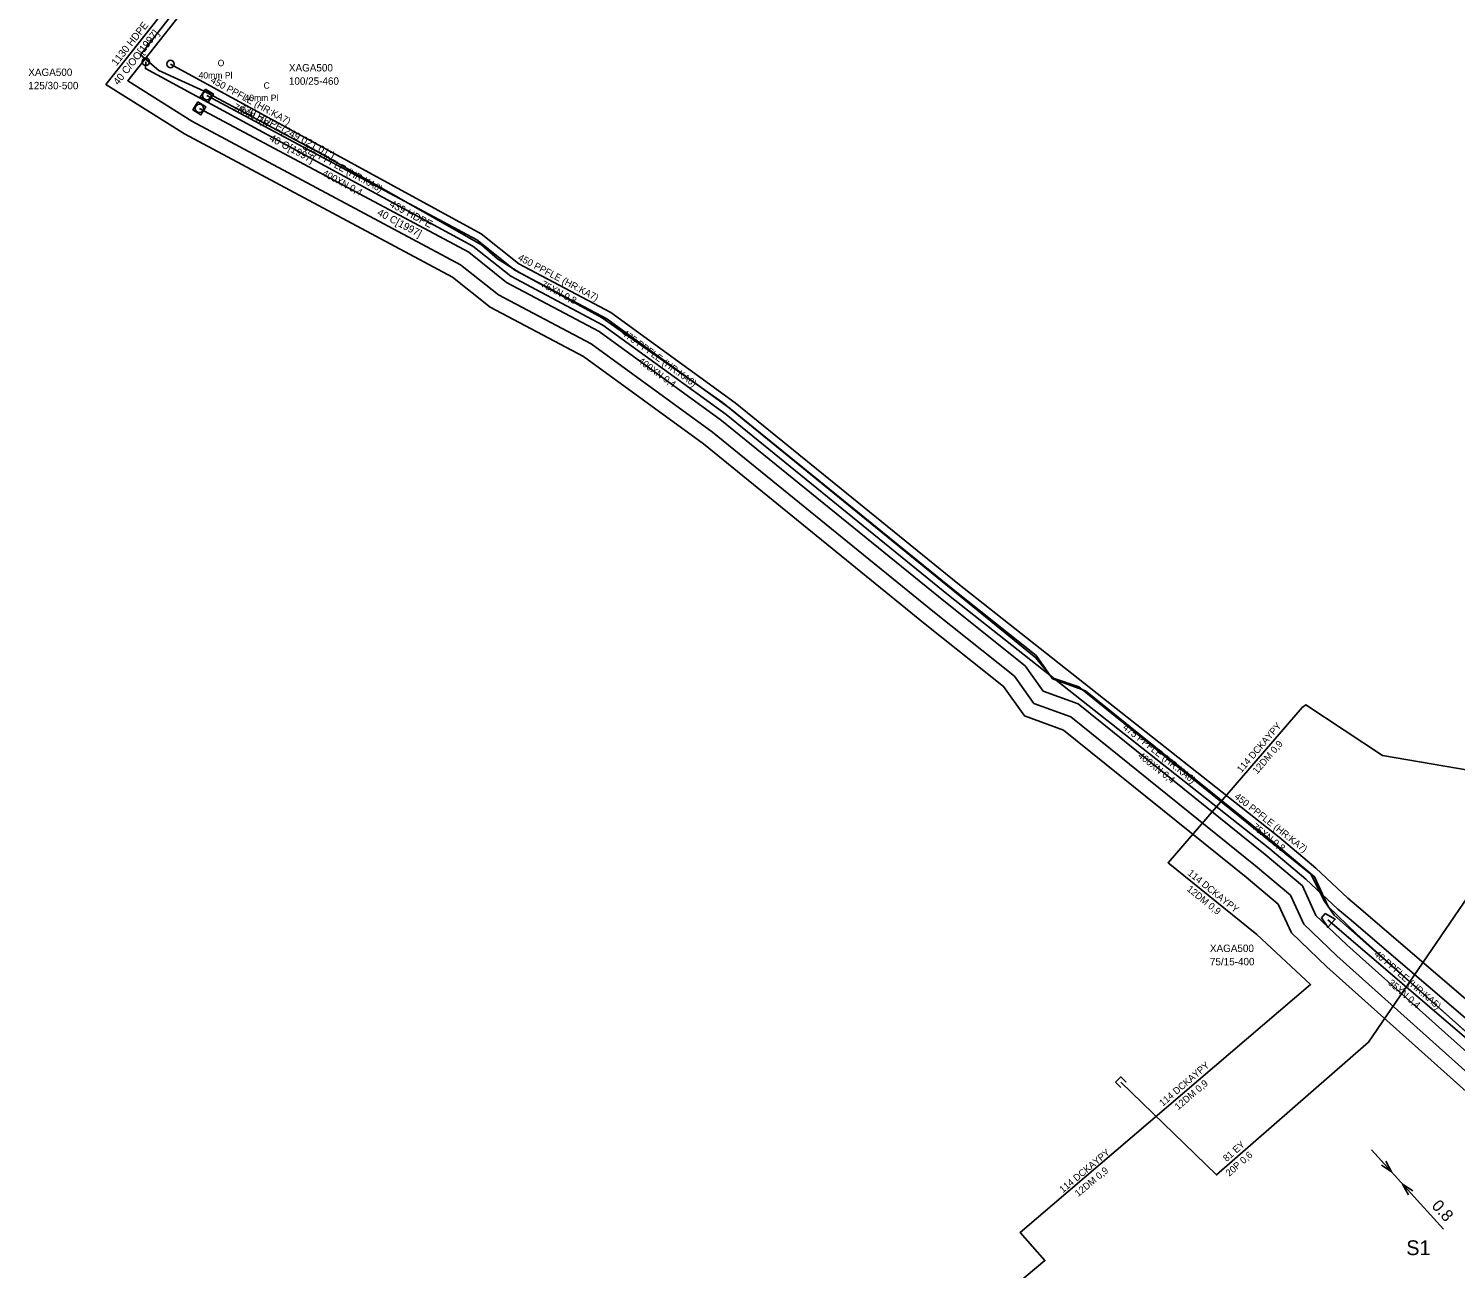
# Model space of a CAD drawing. Extents: x -756413 to -755757, y -1139003 to -1138237.
# Drawn here: x -756377.9 to -756305.6, y -1138368.5 to -1138305.7 of the extents above; entities that cross this region are included whole.
import ezdxf

# ---------------------------------------------------------------- set-up
doc = ezdxf.new("R2010")
doc.units = 0
for name, color, linetype in [('f004_popisy_mts', 7, 'Continuous'), ('f006_osa_trasy', 7, 'Continuous'), ('f006_stp_koty', 7, 'Continuous'), ('f307_kabel_metal', 7, 'Continuous'), ('f307_kabel_metal_ann', 7, 'Continuous'), ('f307_rozvadec', 7, 'Continuous'), ('f307_spojka_metal', 7, 'Continuous'), ('f307_spojka_metal_ann', 7, 'Continuous'), ('f309_trubka', 7, 'Continuous'), ('f309_trubka_ann', 7, 'Continuous'), ('f309_trubkova_spojka', 7, 'Continuous'), ('f309_trubkova_spojka_ann', 7, 'Continuous')]:
    doc.layers.add(name, color=color, linetype=linetype)

msp = doc.modelspace()

# ---------------------------------------------------------------- linework, layer by layer
at = {"layer": 'f006_osa_trasy'}
for p, q in [((-756372.2, -1138307), (-756367.32, -1138300.71)), ((-756371.27, -1138307.79), (-756372.2, -1138307)), ((-756368.97, -1138308.84), (-756371.27, -1138307.79))]:
    msp.add_line(p, q, dxfattribs=at)
for points in [[(-756311.7, -1138350.6), (-756312.2, -1138349.89), (-756312.88, -1138348.52), (-756324.64, -1138339.04), (-756326, -1138338.58), (-756326.82, -1138337.56), (-756342.7, -1138324.62), (-756348.8, -1138320.32), (-756353.03, -1138318.01), (-756354.11, -1138317.34), (-756354.92, -1138316.62), (-756363.09, -1138311.98), (-756368.97, -1138308.84)], [(-756282.83, -1138375.12), (-756286.84, -1138371.72), (-756290.36, -1138368.73), (-756302.28, -1138358.38), (-756303.67, -1138357.72), (-756311.7, -1138350.6)]]:
    msp.add_lwpolyline(points, dxfattribs=at)
at = {"layer": 'f006_stp_koty'}
msp.add_line((-756306.164, -1138366.516), (-756309.809, -1138362.51), dxfattribs=at)
for points in [[(-756309.091, -1138363.075), (-756308.799, -1138363.62), (-756309.313, -1138363.277)], [(-756307.941, -1138364.786), (-756308.234, -1138364.242), (-756307.719, -1138364.584)]]:
    msp.add_lwpolyline(points, dxfattribs=at)
at = {"layer": 'f307_kabel_metal'}
msp.add_line((-756312.023, -1138350.844), (-756283.054, -1138375.657), dxfattribs=at)
for points in [[(-756371.931, -1138307.344), (-756371.951, -1138307.693), (-756355.352, -1138316.692), (-756353.441, -1138318.219), (-756348.762, -1138320.694), (-756342.525, -1138325.233), (-756331.254, -1138334.386), (-756314.973, -1138347.236), (-756313.134, -1138348.782), (-756311.511, -1138350.296), (-756310.942, -1138350.783), (-756282.566, -1138375.087)], [(-756370.682, -1138307.46), (-756354.935, -1138316.065), (-756353.028, -1138317.589), (-756348.364, -1138320.056), (-756342.068, -1138324.638), (-756330.785, -1138333.801), (-756314.499, -1138346.654), (-756312.637, -1138348.22), (-756311.011, -1138349.737), (-756310.454, -1138350.213), (-756282.069, -1138374.526)], [(-756262.57, -1138317.363), (-756260.496, -1138324.127), (-756259.505, -1138325.18), (-756259.777, -1138325.43), (-756263.526, -1138328.915), (-756272.962, -1138335.593), (-756279.837, -1138339.642), (-756286.212, -1138342.863), (-756292.891, -1138344.13), (-756301.068, -1138343.923), (-756309.263, -1138342.52), (-756313.137, -1138339.946), (-756313.333, -1138340.073), (-756320.121, -1138347.951), (-756315.62, -1138351.591), (-756312.901, -1138354.115), (-756327.623, -1138366.698), (-756326.363, -1138368.116), (-756330.364, -1138371.464)], [(-756322.516, -1138359.073), (-756317.669, -1138363.776), (-756309.965, -1138357.043), (-756301.946, -1138345.295), (-756301.214, -1138345.42), (-756292.769, -1138345.634), (-756285.724, -1138344.297), (-756279.117, -1138340.959), (-756272.147, -1138336.854), (-756262.578, -1138330.082), (-756258.759, -1138326.532), (-756258.49, -1138326.284), (-756255.749, -1138329.169), (-756255.255, -1138329.693), (-756254.586, -1138330.522), (-756254.548, -1138330.753)]]:
    msp.add_lwpolyline(points, dxfattribs=at)
at = {"layer": 'f307_rozvadec'}
msp.add_lwpolyline([(-756322.251, -1138359.068), (-756322.521, -1138358.808), (-756322.781, -1138359.078), (-756322.511, -1138359.338)], dxfattribs=at)
at = {"layer": 'f307_spojka_metal'}
msp.add_lwpolyline([(-756312.156, -1138350.528), (-756311.648, -1138350.809), (-756312.032, -1138351.22), (-756312.348, -1138350.734)], close=True, dxfattribs=at)
for centre in [(-756371.931, -1138307.344), (-756370.682, -1138307.46)]:
    msp.add_circle(centre, 0.188, dxfattribs=at)
at = {"layer": 'f309_trubka'}
for points in [[(-756366.687, -1138299.301), (-756373.952, -1138308.498), (-756369.971, -1138311.006), (-756356.391, -1138318.262), (-756354.473, -1138319.794), (-756349.757, -1138322.289), (-756343.668, -1138326.72), (-756332.428, -1138335.847), (-756328.46, -1138339.009), (-756327.402, -1138340.502), (-756325.425, -1138341.221), (-756316.162, -1138348.687), (-756314.536, -1138350.053), (-756313.872, -1138351.504), (-756312.079, -1138353.218), (-756304.862, -1138359.682)], [(-756366.164, -1138299.849), (-756372.846, -1138308.308), (-756369.594, -1138310.357), (-756355.977, -1138317.633), (-756354.06, -1138319.164), (-756349.359, -1138321.651), (-756343.211, -1138326.125), (-756331.958, -1138335.263), (-756327.91, -1138338.489), (-756326.926, -1138339.877), (-756325.051, -1138340.559), (-756315.685, -1138348.108), (-756313.924, -1138349.587), (-756313.25, -1138351.061), (-756311.57, -1138352.667), (-756304.444, -1138359.049)], [(-756368.84, -1138309.059), (-756355.149, -1138316.375), (-756353.234, -1138317.904), (-756348.563, -1138320.375), (-756342.297, -1138324.935), (-756331.018, -1138334.095), (-756326.81, -1138337.449), (-756325.974, -1138338.627), (-756324.303, -1138339.235), (-756314.733, -1138346.95), (-756312.7, -1138348.655), (-756312.006, -1138350.175), (-756310.552, -1138351.565), (-756303.608, -1138357.783)], [(-756369.217, -1138309.708), (-756355.563, -1138317.004), (-756353.647, -1138318.534), (-756348.961, -1138321.013), (-756342.754, -1138325.53), (-756331.488, -1138334.679), (-756327.36, -1138337.969), (-756326.45, -1138339.252), (-756324.677, -1138339.897), (-756315.209, -1138347.529), (-756313.312, -1138349.121), (-756312.628, -1138350.618), (-756311.061, -1138352.116), (-756304.026, -1138358.416)]]:
    msp.add_lwpolyline(points, dxfattribs=at)
at = {"layer": 'f309_trubkova_spojka'}
for points in [[(-756368.915, -1138308.728), (-756369.171, -1138309.134), (-756368.765, -1138309.39), (-756368.509, -1138308.984)], [(-756369.292, -1138309.377), (-756369.548, -1138309.783), (-756369.142, -1138310.039), (-756368.886, -1138309.633)]]:
    msp.add_lwpolyline(points, close=True, dxfattribs=at)
for centre in [(-756368.84, -1138309.059), (-756369.217, -1138309.708)]:
    msp.add_circle(centre, 0.216, dxfattribs=at)

# ---------------------------------------------------------------- texts
at = {"layer": 'f004_popisy_mts'}
msp.add_text('S1', height=0.75, dxfattribs=at).set_placement((-756308.05, -1138367.84))
at = {"layer": 'f006_stp_koty'}
msp.add_text('0.8', height=0.6, rotation=312.3, dxfattribs=at).set_placement((-756306.801, -1138365.37))
at = {"layer": 'f307_kabel_metal_ann'}
for s, rotation, p in [('450 PPFLE (HR:KA7)', 331.35, (-756368.683, -1138308.382)), (' 75XN 0,8', 331.35, (-756367.65, -1138309.687)), ('475 PPFLE (HR:KA6)', 331.54, (-756364.023, -1138311.821)), (' 400XN 0,4', 331.54, (-756363.138, -1138313.039)), ('450 PPFLE (HR:KA7)', 332.12, (-756353.106, -1138317.378)), (' 75XN 0,8', 332.12, (-756352.055, -1138318.669)), ('475 PPFLE (HR:KA6)', 323.95, (-756347.834, -1138321.184)), (' 400XN 0,4', 323.95, (-756347.118, -1138322.509)), ('475 PPFLE (HR:KA6)', 321.72, (-756322.446, -1138341.147)), ('114 DCKAYPY', 49.25, (-756316.409, -1138343.413)), (' 12DM 0,9', 49.25, (-756315.691, -1138343.575)), (' 400XN 0,4', 321.72, (-756321.782, -1138342.499)), ('450 PPFLE (HR:KA7)', 321.72, (-756316.792, -1138344.653)), (' 75XN 0,8', 321.72, (-756315.992, -1138346.113)), ('114 DCKAYPY', 321.04, (-756319.162, -1138348.534)), (' 12DM 0,9', 321.04, (-756319.302, -1138349.257)), ('40 PPFLE (HR:KA5)', 319.42, (-756309.709, -1138352.628)), (' 35XN 0,4', 319.42, (-756309.1, -1138354.005)), ('114 DCKAYPY', 40.52, (-756320.39, -1138360.318)), (' 12DM 0,9', 40.52, (-756319.705, -1138360.587)), ('81 EY', 41.15, (-756317.154, -1138363.126)), ('114 DCKAYPY', 39.68, (-756325.456, -1138364.706)), (' 20P 0,6', 41.15, (-756317.119, -1138363.959)), (' 12DM 0,9', 39.68, (-756324.775, -1138364.985))]:
    msp.add_text(s, height=0.35, rotation=rotation, dxfattribs=at).set_placement(p)
at = {"layer": 'f307_spojka_metal_ann'}
for s, p in [('XAGA500', (-756377.888, -1138308.065)), ('XAGA500', (-756364.681, -1138307.837)), ('125/30-500', (-756377.888, -1138308.74)), ('100/25-460', (-756364.681, -1138308.512)), ('XAGA500', (-756318.002, -1138352.473)), ('75/15-400', (-756318.002, -1138353.148))]:
    msp.add_text(s, height=0.375, dxfattribs=at).set_placement(p)
at = {"layer": 'f309_trubka_ann'}
for s, rotation, p in [('1130 HDPE', 51.69, (-756373.417, -1138307.579)), ('40 C/OO[1997]', 51.69, (-756373.329, -1138308.557)), ('439 HDPE(249 021 01;)', 331.88, (-756367.199, -1138309.766)), ('40 O[1997]', 331.88, (-756365.712, -1138311.325)), ('40 C[1997]', 331.88, (-756360.239, -1138315.1)), ('439 HDPE', 331.88, (-756359.62, -1138314.666))]:
    msp.add_text(s, height=0.375, rotation=rotation, dxfattribs=at).set_placement(p)
at = {"layer": 'f309_trubkova_spojka_ann'}
for s, p in [('40mm Pl', (-756369.258, -1138308.195)), ('O', (-756368.291, -1138307.57)), ('C', (-756365.964, -1138308.712)), ('40mm Pl', (-756366.931, -1138309.337))]:
    msp.add_text(s, height=0.325, dxfattribs=at).set_placement(p)

doc.saveas('drawing.dxf')
